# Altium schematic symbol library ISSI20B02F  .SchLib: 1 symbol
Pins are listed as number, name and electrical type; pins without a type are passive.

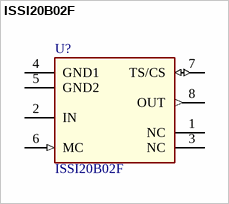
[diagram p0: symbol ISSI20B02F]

## ISSI20B02F
designator U?
coreless-transformer advanced solid-state isolators; Manufacturer: Infineon Technologies
pins: 1 NC "Not connected", 2 IN (power) "Supply and non-inverting control input", 3 NC "Not connected", 4 GND1 (power) "Reference of control side", 5 GND2 (power) "Reference of output side", 6 MC (in) "Miller clamp input", 7 TS/CS (io) "Output for temperature sensor bias current and input for sensed signal", 8 OUT (out) "Gate drive output"
1 alternate drawing of the same symbol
